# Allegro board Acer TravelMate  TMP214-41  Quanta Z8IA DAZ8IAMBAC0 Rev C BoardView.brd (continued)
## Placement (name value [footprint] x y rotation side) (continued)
C96764  2.2u/10V_4  [C0402]  92.37 113.94 270 top
C96765  10u/6.3V_4  [C0402]  133.9 131.21 90 top
C96766  47u/6.3V_6  [C0603]  117.8 119.91 0 top
C96767  4.7u/6.3V_4  [C0402]  111.42 116.99 90 bottom
C96768  1u/10V_2  [C0201]  107.95 130.6 270 top
C96769  1u/10V_2  [C0201]  105.71 111.27 0 top
C96770  0.1u/6.3V_2  [C0201]  105.71 112.04 0 top
C96771  *1u/10V_2  [C0201]  105.71 110.51 0 top
C96772  *1u/10V_2  [C0201]  104.57 112.16 180 top
C96773  1u/10V_2  [C0201]  103.88 109.88 270 bottom
C96774  0.1u/6.3V_2  [C0201]  103.55 111.91 270 bottom
C96776  HUB@0.1u/6.3V_2  [C0201]  77.29 117.37 270 top
C96777  HUB@22p/25V_2  [C0201]  85.39 112.87 90 top
C96778  HUB@22p/25V_2  [C0201]  85.39 111.07 270 top
C96779  HUB@1u/10V_2  [C0201]  82.39 116.74 90 top
C96780  HUB@0.1u/6.3V_2  [C0201]  81.33 107.51 0 top
C96781  HUB@0.1u/6.3V_2  [C0201]  77.26 110.26 90 top
C96782  HUB@1u/10V_2  [C0201]  85.77 114.45 180 top
C96783  HUB@1u/10V_2  [C0201]  81.33 108.23 0 top
C96784  HUB@0.1u/6.3V_2  [C0201]  85.26 110.21 180 top
C96785  HUB@10u/6.3V_4  [C0402]  85.64 115.34 0 top
C96786  HUB@0.1u/6.3V_2  [C0201]  76.5 110.26 90 top
C96788  SM@470p/50V_4  [C0402]  224.07 91.72 90 top
C96789  SM@0.1u/6.3V_2  [C0201]  225.09 91.46 270 top
C96790  SM@22u/6.3V_6  [C0603]  226.87 91.21 0 top
C96791  0.1u/6.3V_2  [C0201]  128.06 140.74 90 bottom
C96792  0.1u/6.3V_2  [C0201]  128.82 140.74 90 bottom
C96793  0.1u/6.3V_2  [C0201]  120.31 108.99 270 bottom
C96794  1u/10V_2  [C0201]  131.24 103.65 270 bottom
C96795  22p/25V_2  [C0201]  120.31 106.45 270 bottom
C96796  100p/50V_2  [C0201]  169.59 98.29 90 top
C96797  1000p/25V_2  [C0201]  170.73 101.22 90 top
C96798  0.22u/25V_2  [C0201]  24.72 64.65 180 top
C96799  0.22u/25V_2  [C0201]  24.72 65.41 180 top
C96800  0.22u/25V_2  [C0201]  24.72 66.17 180 top
C96801  0.33u/25V_2  [C0201]  11.73 70.25 180 bottom
C96802  0.33u/25V_2  [C0201]  11.73 69.49 180 bottom
C96803  0.22u/25V_2  [C0201]  24.72 63.88 180 top
C96804  0.22u/25V_2  [C0201]  11.73 70.25 180 top
C96805  0.22u/25V_2  [C0201]  11.73 69.49 180 top
C96806  0.22u/25V_2  [C0201]  24.72 61.6 180 top
C96807  0.22u/25V_2  [C0201]  24.72 60.84 180 top
C96808  0.33u/25V_2  [C0201]  11.73 62.25 180 top
C96809  0.33u/25V_2  [C0201]  11.73 63.01 180 top
C96810  0.22u/25V_2  [C0201]  24.72 62.36 180 top
C96811  0.22u/25V_2  [C0201]  24.72 63.12 180 top
C96812  0.22u/25V_2  [C0201]  11.73 62.25 180 bottom
C96813  0.22u/25V_2  [C0201]  11.73 63.01 180 bottom
C96814  10p/25V_2  [C0201]  20.11 68.09 180 top
C96815  10p/25V_2  [C0201]  18.99 68.09 0 top
C96816  2.2u/10V_4  [C0402]  19.98 63.55 0 bottom
C96817  47u/6.3V_6  [C0603]  22.8 68.35 270 bottom
C96818  2.2u/10V_4  [C0402]  21.48 67.92 270 bottom
C96819  2.2u/10V_4  [C0402]  23.03 65.55 270 bottom
C96820  2.2u/10V_4  [C0402]  21.76 63.52 180 bottom
C96821  2.2u/10V_4  [C0402]  17.85 67.21 90 bottom
C96822  10u/6.3V_4  [C0402]  16.89 67.21 90 bottom
C96823  18p/25V_2  [C0201]  18.84 66.8 270 bottom
C96824  2.2u/10V_4  [C0402]  23.13 63.8 270 bottom
C96825  10u/6.3V_4  [C0402]  20.11 66.82 180 bottom
C96826  2.2u/10V_4  [C0402]  19.73 68.22 180 bottom
C96827  47u/6.3V_6  [C0603]  23.67 73.43 90 top
C96828  18p/25V_2  [C0201]  25.45 75.46 180 top
C96829  47u/6.3V_6  [C0603]  22.25 73.43 90 top
C96830  2.2u/10V_4  [C0402]  23.03 62 270 bottom
C96831  2.2u/10V_4  [C0402]  18.33 65.43 90 bottom
C96832  2.2u/10V_4  [C0402]  18.33 63.65 90 bottom
C96833  2.2u/10V_4  [C0402]  18.33 61.87 270 bottom
C96834  2.2u/10V_4  [C0402]  16.94 65.43 90 bottom
C96835  47u/6.3V_6  [C0603]  33.19 65.43 90 top
C96836  2.2u/10V_4  [C0402]  29 64.28 270 top
C96837  0.1u/6.3V_2  [C0201]  33.57 71.14 0 top
C96851  47u/6.3V_6  [C0603]  5.3 45.79 90 bottom
C96852  47u/6.3V_6  [C0603]  6.75 45.77 90 bottom
C96853  47u/6.3V_6  [C0603]  8.17 45.79 90 bottom
C96854  10u/6.3V_4  [C0402]  8.81 47.6 0 bottom
C96855  10u/25V_8  [C0805]  10.46 52.47 270 bottom
C96856  0.47u/25V_2  [C0201]  11.09 67.92 90 top
C96857  0.47u/25V_2  [C0201]  10.43 64.67 180 top
C96858  0.47u/25V_2  [C0201]  10.33 67.92 90 top
C96859  0.47u/25V_2  [C0201]  10.43 65.38 180 top
C96861  1u/10V_2  [C0201]  14.45 55.14 180 bottom
C96862  1u/10V_2  [C0201]  13.89 45.18 270 bottom
C96863  0.1u/25V_2  [C0201]  14.45 55.9 180 bottom
C96864  0.1u/25V_2  [C0201]  15.54 55.9 0 bottom
C96865  0.1u/25V_2  [C0201]  14.65 45.18 270 bottom
C96866  1u/10V_2  [C0201]  15.54 55.14 0 bottom
C96867  390p/50V_4  [C0402]  22.65 48.66 0 bottom
C96868  390p/50V_4  [C0402]  22.65 47.65 0 bottom
C96869  0.1u/25V_2  [C0201]  22.27 46.76 0 bottom
C96870  **0.1u/6.3V_2  [C0201]  205.02 116.35 90 bottom
C96871  10u/6.3V_4  [C0402]  194.99 104.8 0 bottom
C96872  0.1u/6.3V_2  [C0201]  194.23 103.4 90 bottom
C96873  0.01u/10V_2  [C0201]  194.99 103.4 90 bottom
C96876  47u/6.3V_8  [C0805]  199.05 120.93 0 bottom
C96878  **1000p/25V_2  [C0201]  204.26 116.35 90 bottom
C96879  EX-IO@0.1u/6.3V_2  [C0201]  133.9 127.53 0 bottom
C96880  EX-IO@0.1u/6.3V_2  [C0201]  135.94 118.03 90 bottom
C96881  EX-IO@1u/10V_2  [C0201]  139.49 120.8 0 bottom
C96882  22u/6.3V_6  [C0603]  208.33 123.72 0 bottom
C96883  *0.1u/6.3V_2  [C0201]  204.26 113.81 180 top
C96884  *0.1u/6.3V_2  [C0201]  205.15 108.73 270 top
C96885  *1000p/25V_2  [C0201]  209.24 118.28 180 bottom
C96886  0.047u/25V_4  [C0402]  209.14 119.15 0 bottom
C96887  0.1u/6.3V_2  [C0201]  207.77 119.25 180 bottom
C96888  *10u/6.3V_4  [C0402]  207.41 118.39 0 bottom
C96889  0.1u/6.3V_2  [C0201]  207.18 113.81 0 top
C96890  0.1u/6.3V_2  [C0201]  209.47 113.81 0 top
C96891  *debug2@0.1u/6.3V_2  [C0201]  168.7 141.25 0 top
C96892  22u/6.3V_6  [C0603]  170.1 137.31 0 bottom
C96893  *1000p/25V_2  [C0201]  166.8 139.72 90 bottom
C96894  0.1u/6.3V_2  [C0201]  167.79 147.93 180 top
C96895  0.1u/6.3V_2  [C0201]  166.8 140.74 270 bottom
C96896  *10u/6.3V_4  [C0402]  165.91 140.36 90 bottom
C96897  *0.1u/6.3V_2  [C0201]  169.72 141.25 180 top
C96898  *0.1u/6.3V_2  [C0201]  171.01 145.18 90 bottom
C96901  2.2u/10V_4  [C0402]  33.57 70.25 0 top
C96902  2.2u/10V_4  [C0402]  28.62 65.68 180 top
C96903  0.1u/6.3V_2  [C0201]  77.85 101.37 0 top
C96904  *0.1u/6.3V_2  [C0201]  170.86 146.2 0 bottom
C96905  0.33u/25V_2  [C0201]  81.96 121.43 270 top
C96906  2.2u/10V_4  [C0402]  30.65 40.79 270 bottom
C96907  SPIN@0.1u/6.3V_2  [C0201]  142.03 213.48 0 top
C96908  *100p/50V_2  [C0201]  3.98 53.11 180 bottom
C96909  6800p/50V_4  [C0402]  3.98 54 0 bottom
C96910  0.1u/25V_2  [C0201]  3.98 48.59 0 bottom
C96911  0.1u/25V_2  [C0201]  3.98 51.58 0 bottom
C96912  *EX-IO@0.1u/6.3V_2  [C0201]  139.24 127.02 90 bottom
C96913  *EX-IO@0.1u/6.3V_2  [C0201]  135.81 130.32 0 bottom
C96918  **HDD_MS@0.1u/6.3V_2  [C0201]  232.07 125.63 0 top
C96919  *HDD_MS@0.1u/6.3V_2  [C0201]  232.84 120.93 0 top
C96920  **HDD_MS@0.1u/6.3V_2  [C0201]  216.2 104.67 180 top
C96921  *HDD_MS@0.1u/6.3V_2  [C0201]  218.87 108.1 180 top
C96922  I219@0.1u/6.3V_2  [C0201]  16.38 164.23 90 bottom
C96923  I219@0.1u/6.3V_2  [C0201]  14.9 164.23 90 bottom
C96924  I219@0.1u/6.3V_2  [C0201]  14.14 164.23 90 bottom
C96925  ViKi@1000p/25V_2  [C0201]  44.5 96.54 90 top
C96926  ViKi@1000p/25V_2  [C0201]  43.48 96.54 90 top
C96927  ViKi@1000p/25V_2  [C0201]  42.21 96.16 0 top
C96928  ViKi@1000p/25V_2  [C0201]  46.02 96.67 180 top
C96929  **SSD_MS@0.1u/6.3V_2  [C0201]  18.08 78.89 90 top
C96930  *SSD_MS@0.1u/6.3V_2  [C0201]  23.67 77.24 180 top
C96931  0.1u/6.3V_2  [C0201]  106.98 111.32 0 bottom
CN1  50271-0020N-001  [50271-00201-001-2P-L]  6.3 10.83 270 bottom
CN2  USB-097-1R09HG  [UB3-USB-097-1R09HG-9P]  8.4 89.12 90 bottom
CN3  USB-097-1R09HG  [UB3-USB-097-1R09HG-9P]  8.4 107.22 90 bottom
CN4  SPIN@50506-0060N-V01  [FPC-50506-0060N-V01-6P-L]  85.9 96.8 180 bottom
CN8  2RJ1622-001111F  [RJ45-2RJ1622-001111F-8P]  11.05 184.7 90 bottom
CN10  560Q10-010H  [UB31-560Q10-010H-24P]  8.51 66.67 90 bottom
CN11  HDD@GS12201-1011-7H  [WTB-GS12201-1011-7H-20P-L-SMT]  229.89 105.5 0 bottom
CN13  50505-00401-V01  [50505-00401-V01-4P-L]  224.85 135.4 270 bottom
CN14  SPIN_N@196241-08021-3  [196241-08021-3-8P-L]  75.7 96.95 180 bottom
CN16  SSD@NASM0-S6701-TSH4  [NGFF-NASM0-S6701-TSH4-KM-SMT]  25.1 75.1 180 bottom
CN17  NASE0-S6701-TS40  [NGFF-NASE0-S6701-TS40-KE-SMT]  189.65 114.4 270 bottom
CN18  15@50584-0280N-V02  [50584-0280N-V02-28P-L]  182.54 98.8 180 bottom
CN19  14@50584-0280N-V02  [50584-0280N-V02-28P-L]  154.9 108 180 bottom
CN21  CRT@DHR4U-15K1202  [DSUB-DHR4U-15K1202-15P]  7.6 157.76 90 bottom
CN29  196538-40041-3  [196538-40041-3-40P-L]  66.4 196.1 0 bottom
CN33  196047-08021-3  [196047-08021-3-8P-L]  129.6 97.05 180 bottom
CN37  10591-19001  [HDMI-10591-19001-19P]  4.4 127.48 90 bottom
CN46  SPIN@50271-0020N-001  [50271-00201-001-2P-L]  52.1 95.9 180 bottom
CN48  P2_P2SPIN@51540-02201-V01  [FPC-51540-02201-V01-22P-L]  207.2 110.12 180 bottom
CN49  LTE@51540-03001-V01  [51540-03001-V01-30P-L]  225.75 120.5 270 bottom
CN50  IR@50208-00601-V02  [50208-00601-V02-6P-L]  34.57 195.85 0 bottom
CN51  2SJ3127-023111F  [AUDIO-2SJ3127-023111F-6P]  5.42 21.46 90 bottom
CN52  SPIN@51619-01601-V01  [51619-01601-V01-16P-L]  207.1 98.15 180 bottom
CN53  SM@51653-0100N-V01  [51653-0100N-V01-10P-L]  222.4 98.05 180 bottom
CN55  ViKi@51619-01601-V01  [51619-01601-V01-16P-L]  231.85 121.21 270 bottom
CN58  NFC@51619-01501-V03  [51619-01501-V03-15P-L]  64.2 96.85 180 bottom
CN62  156-1000302610  [SDCARD-156-1000302610-11P-SMT]  13.3 43.05 270 top
CN63  P2_P2SPIN@50271-0040N-V01  [50271-0040N-V01-4P-L]  92.15 202.83 90 bottom
CN64  ViKi@50271-0040N-V01  [50271-0040N-V01-4P-L]  41.5 94.87 180 bottom
CN66  debug@51614-00601-V01  [51614-00601-V01-6P-L]  205.15 92.1 0 top
CN67  SPIN@50208-00601-V02  [50208-00601-V02-6P-L]  50.5 199.85 0 bottom
D3  1N4148WS  [D-SOD323-1_85X1_25-0_95H]  86.56 192.6 270 bottom
D4  EV@RB500V-40  [D-SOD323-1_85X1_25-0_95H]  108.76 185.32 90 top
D10  AZ5725-01F.R7G  [ESD-1X0_6-2P]  4.04 14.75 180 top
D11  1N4148WS  [D-SOD323-1_85X1_25-0_95H]  24.93 24.22 270 bottom
D12  *RB500V-40  [D-SOD323-1_85X1_25-0_95H]  32.56 31.77 180 bottom
D13  RB500V-40  [D-SOD323-1_85X1_25-0_95H]  32.56 33.68 180 bottom
D22  *PESD5V0H1BSF  [D-0_6X0_3-0_32H-SMT]  92.38 99.08 270 top
D33  AZ5725-01F.R7G  [ESD-1X0_6-2P]  194.74 97.69 0 top
D50  AZ5725-01F.R7G  [ESD-1X0_6-2P]  15.01 129.9 90 bottom
D51  *RB500V-40  [D-SOD323-1_85X1_25-0_95H]  141.17 103.91 180 top
D60  *RB500V-40  [D-SOD323-1_85X1_25-0_95H]  141.17 102 180 top
D62  *RB500V-40  [D-SOD323-1_85X1_25-0_95H]  141.27 100.1 0 top
D63  RB500V-40  [D-SOD323-1_85X1_25-0_95H]  144.95 103.93 0 top
D64  *RB500V-40  [D-SOD323-1_85X1_25-0_95H]  141.45 105.79 180 top
D65  TVM0G5R5M220R_22p  [R0402]  160.68 115.29 270 top
D72  BAT54CW  [SOT23-1_7-65-3P]  77.9 98.7 270 top
D6543  1N4148WS  [D-SOD323-1_85X1_25-0_95H]  23.07 22.5 270 bottom
D13081  *PESD5V0H1BSF  [D-0_6X0_3-0_32H-SMT]  15.67 126.97 270 bottom
D13082  *PESD5V0H1BSF  [D-0_6X0_3-0_32H-SMT]  15.67 125.93 90 bottom
D13083  *PESD5V0H1BSF  [D-0_6X0_3-0_32H-SMT]  15.45 125.54 0 top
D13084  *PESD5V0H1BSF  [D-0_6X0_3-0_32H-SMT]  15.45 124.48 0 top
D13085  *PESD5V0H1BSF  [D-0_6X0_3-0_32H-SMT]  15.01 121.92 0 top
D13086  *PESD5V0H1BSF  [D-0_6X0_3-0_32H-SMT]  15.01 120.86 0 top
D13087  *PESD5V0H1BSF  [D-0_6X0_3-0_32H-SMT]  15.52 128.84 0 top
D13088  *PESD5V0H1BSF  [D-0_6X0_3-0_32H-SMT]  15.52 127.75 0 top
D13089  *PESD5V0H1BSF  [D-0_6X0_3-0_32H-SMT]  14.52 131.21 270 top
D13090  *PESD5V0H1BSF  [D-0_6X0_3-0_32H-SMT]  14.52 130.07 90 top
D13091  *TVM0G5R5M220R_22p  [R0402]  147.62 209.57 0 top
D13092  *TVM0G5R5M220R_22p  [R0402]  151.05 210.72 180 top
D13093  SPIN_EXT@RB500V-40  [D-SOD323-1_85X1_25-0_95H]  155.49 212.87 180 bottom
D13094  AZ5725-01F.R7G  [ESD-1X0_6-2P]  7.06 29.98 90 bottom
D13095  AZ5725-01F.R7G  [ESD-1X0_6-2P]  11.09 14.37 270 top
D13096  P4SMAFJ20A  [D-3_8X2_5]  11.43 57.93 90 bottom
D13101  TVM0G5R5M261R_260p  [R0402]  18 88.92 90 bottom
D13102  TVM0G5R5M261R_260p  [R0402]  18.59 110.97 180 top
D13106  RB500V-40  [D-SOD323-1_85X1_25-0_95H]  92.07 109.14 0 top
D13107  RB500V-40  [D-SOD323-1_85X1_25-0_95H]  94.74 108.1 270 top
D13108  *RB500V-40  [D-SOD323-1_85X1_25-0_95H]  97.35 107.46 90 top
D13110  *HUB@SDM20U30-7  [D-1_2X0_8-0_7H]  84.98 117.5 270 top
D13111  *PESD5V0F1BSF  [D-0_6X0_3-0_32H-SMT]  61.03 191.28 180 bottom
D13112  *PESD5V0F1BSF  [D-0_6X0_3-0_32H-SMT]  59.99 191.28 0 bottom
D13113  *PESD5V0F1BSF  [D-0_6X0_3-0_32H-SMT]  57.55 191.28 0 bottom
D13114  *PESD5V0F1BSF  [D-0_6X0_3-0_32H-SMT]  58.59 191.28 180 bottom
D13118  PESD5V0F1BSF  [D-0_6X0_3-0_32H-SMT]  10.59 72.54 90 bottom
D13119  PESD5V0F1BSF  [D-0_6X0_3-0_32H-SMT]  10.46 65.3 270 bottom
D13142  PESD5V0F1BSF  [D-0_6X0_3-0_32H-SMT]  8.94 67.21 90 top
D13143  PESD5V0F1BSF  [D-0_6X0_3-0_32H-SMT]  8.94 66.09 270 top
D13144  PESD5V0F1BSF  [D-0_6X0_3-0_32H-SMT]  10.46 66.37 270 bottom
D13145  PESD5V0F1BSF  [D-0_6X0_3-0_32H-SMT]  10.46 67.41 90 bottom
D13146  PESD5V0F1BSF  [D-0_6X0_3-0_32H-SMT]  12.62 71.93 90 bottom
D13147  PESD5V0F1BSF  [D-0_6X0_3-0_32H-SMT]  11.35 67.97 270 bottom
D13148  EX-IO@RB500V-40  [D-SOD323-1_85X1_25-0_95H]  142.54 122.7 270 bottom
D13149  *BAT54CW  [SOT23-1_7-65-3P]  202.59 108.86 270 top
D13150  *BAT54CW  [SOT23-1_7-65-3P]  202.61 111.91 270 top
D13151  PESD5V0H1BSF  [D-0_6X0_3-0_32H-SMT]  12.87 70.38 90 bottom
D13152  PESD5V0H1BSF  [D-0_6X0_3-0_32H-SMT]  12.87 69.34 270 bottom
D13153  PESD5V0H1BSF  [D-0_6X0_3-0_32H-SMT]  12.87 70.38 90 top
D13154  PESD5V0H1BSF  [D-0_6X0_3-0_32H-SMT]  12.87 69.34 270 top
D13155  PESD5V0H1BSF  [D-0_6X0_3-0_32H-SMT]  12.87 62.1 270 top
D13156  PESD5V0H1BSF  [D-0_6X0_3-0_32H-SMT]  12.87 63.14 90 top
D13157  PESD5V0H1BSF  [D-0_6X0_3-0_32H-SMT]  12.87 62.1 270 bottom
D13158  PESD5V0H1BSF  [D-0_6X0_3-0_32H-SMT]  12.87 63.14 90 bottom
D13160  RB500V-40  [D-SOD323-1_85X1_25-0_95H]  30.37 44.6 90 bottom
D13161  *EV@RB500V-40  [D-SOD323-1_85X1_25-0_95H]  115.79 178.63 180 top
D13162  PESD5V0F1BSF  [D-0_6X0_3-0_32H-SMT]  18.54 87.88 270 top
D13163  PESD5V0F1BSF  [D-0_6X0_3-0_32H-SMT]  18.54 89.02 90 top
D13164  PESD5V0F1BSF  [D-0_6X0_3-0_32H-SMT]  18.21 104.54 90 top
D13165  PESD5V0F1BSF  [D-0_6X0_3-0_32H-SMT]  18.21 103.4 270 top
DG4  EV@BAT54AW-L  [SOT23-1_7-65-3P]  109.44 176.73 270 bottom
EC5  180p/25V_2  [C0201]  44.3 135.22 90 top
EC6  180p/25V_2  [C0201]  54.81 119.29 90 top
EC7  SPIN_N@AZ5725-01F.R7G  [ESD-1X0_6-2P]  93.39 101.55 270 bottom
EC8  SPIN_N@AZ5725-01F.R7G  [ESD-1X0_6-2P]  93.39 99.72 270 bottom
EC9  SSD@10u/6.3V_4  [C0402]  32.05 68.6 270 bottom
EC10  SSD@10u/6.3V_4  [C0402]  26.46 70.13 0 bottom
EC11  SSD@0.1u/6.3V_2  [C0201]  26.46 69.26 180 bottom
EC16  SPIN@AZ5725-01F.R7G  [ESD-1X0_6-2P]  208.57 99.05 180 top
EC17  SPIN@AZ5725-01F.R7G  [ESD-1X0_6-2P]  206.72 99.05 180 top
ESD3  CRT@AZ1045-04F.R7G  [ESD10-2_5X1-5-9P-AZ1143]  11.35 155.19 90 top
ESD4  CRT@AZ1045-04F.R7G  [ESD10-2_5X1-5-9P-AZ1143]  11.6 159.03 90 top
F1  SMD0603P100SLR_1A_6V  [R0603]  33.07 43.84 270 bottom
F2  SM@SMD0603P100SLR_1A_6V  [R0603]  217.6 103.27 90 top
FAN3  50278-00401-V01  [WTB-50278-00401-V01-4P-L]  176.02 117.8 90 bottom
HE1  APX8132AI-TRG  [SOT23-2_38-95-3P]  148.8 212.35 90 top
HOLE2  EV@H-TBC244IC166D126P2  [H-TBC244IC166D126P2]  116.52 212.65 180 bottom
HOLE3  EV@H-TBC244IC166D126P2  [H-TBC244IC166D126P2]  145.52 173.65 180 bottom
HOLE4  *H-TBC264IC146D146P2  [H-TBC264IC146D146P2]  97.87 114.15 0 top
HOLE5  *H-TBC264IC146D146P2  [H-TBC264IC146D146P2]  132.87 145.16 0 top
HOLE6  *H-TBC264IC146D146P2  [H-TBC264IC146D146P2]  97.87 176.15 0 top
HOLE12  -  [H-TBC236IC166D126P2]  217.95 114.4 180 bottom
HOLE13  *H-TC354IC158BC315D118P2  [H-TC354IC158BC315D118P2]  217.5 129.3 0 top
HOLE14  *h-z8ia-1p2  [H-Z8IA-1P2]  30.7 91.3 0 top
HOLE15  *O-Z8I-2P2  [O-Z8I-2P2]  164.3 216.3 0 top
HOLE16  *O-Z8I-1P2  [O-Z8I-1P2]  124.2 216.3 0 top
HOLE17  *h-z8ia-5p2  [H-Z8IA-5P2]  42.2 197.3 0 top
HOLE18  *H-TBC354IC158D118P2  [H-TBC354IC158D118P2]  177.8 106.58 0 top
HOLE21  *H-C354D177P2  [H-C354D177P2]  234 88.2 0 top
HOLE22  *O-Z8IA-B2P2  [O-Z8IA-B2P2]  12.2 140.3 0 top
HOLE23  *H-C315D118P2  [H-C315D118P2]  8.2 2.5 0 top
HOLE24  *h-z8i-1p2  [H-Z8I-1P2]  5.7 77.2 0 top
HOLE27  *O-Z8IA-B1P2  [O-Z8IA-B1P2]  7 172.36 0 top
HOLE28  *H-C106X87D106X87N  [H-C106X87D106X87N]  3.6 5.75 90 top
HOLE31  *H-C87D87N  [H-C87D87N]  6.8 139.5 0 top
HOLE32  *O-ZI8-3P2  [O-ZI8-3P2]  11.1 208.2 0 top
HOLE33  *2d-barcode-8x8-s  [2D-BARCODE-8X8-S]  30.42 191.28 180 top
HOLE34  *2d-barcode-8x8-s  [2D-BARCODE-8X8-S]  20.26 184.63 90 bottom
HOLE35  *H-S157D157N  [H-S157D157N]  136.16 158.8 0 top
J9007  *JUMP  [JOPEN25X30_S]  82.21 105.94 270 top
JDIM1  D4AS0-26001-1P40  [DDR4-D4AS0-26001-1P40-STD-SMT]  49.23 138.2 270 bottom
JDIM02  D4AR0-26001-1P40  [DDR4-D4AR0-26001-1P40-RVS-SMT]  61.23 138.2 90 bottom
L4  EV@HCB1005KF-330T30_3A  [R0402]  131.56 187.73 0 top
L5  *EV@HCB1608KF-301T20_2A  [R0603]  114.59 192.55 0 top
L6  EV@HCB1005KF-330T30_3A  [R0402]  112.99 190.97 0 top
L7  EV@HCB1005KF-330T30_3A  [R0402]  114.45 195.91 90 top
L8  EV@HCB1005KF-330T30_3A  [R0402]  114.45 197.64 270 top
L11  BLM15AG121SN1D_0.5A  [R0402]  172.89 101.88 180 top
L12  BLM15AG601SN1D_0.3A  [R0402]  52.12 191.92 0 bottom
L13  BLM15AG601SN1D_0.3A  [R0402]  52.12 190.9 0 bottom
L15  PBY160808T-600Y-N_3A  [R0603]  23 40.75 0 bottom
L16  HCB2012KF-220T60_6A  [R0805]  10.7 31.76 180 bottom
L17  CRT@PBY160808T-600Y-N_3A  [R0603]  28.62 145.82 270 top
L22  CRT@BLM15BB470SN1D_0.3A  [R0402]  17.44 153.06 0 top
L23  HCB1005KF-330T30_3A  [R0402]  134.41 96.8 90 top
L24  HCB1005KF-330T30_3A  [R0402]  131.69 96.47 0 top
L27  CRT@BLM15BB470SN1D_0.3A  [R0402]  17.71 154.73 0 top
L28  HCB1608KF-121T30_3A  [R0603]  14.85 38.38 180 bottom
L29  BLM15AG121SN1D_0.5A  [R0402]  172.92 100.86 0 top
L30  BLM15AG121SN1D_0.5A  [R0402]  150.16 112.29 90 top
L31  CRT@BLM15BB470SN1D_0.3A  [R0402]  18.22 156.47 0 top
L4000  I219@4.7uH_3.2x2.5x2  [L3_2X2_5-3_2]  14.9 160.68 0 bottom
L4001  0.68uH_2.5x2.0x1.2  [L2_5X2-1_2H]  25.83 73.48 90 top
L4002  BLM15PD121SN1D_1.3A  [R0402]  28.62 66.7 0 top
L4003  CRT@PBY160808T-600Y-N_3A  [R0603]  36.88 148.43 0 top
LH1  NFP0QHB372HS2D  [FILTER-NFG0QHB372HS2D-4P-SMT]  18.84 129.44 180 top
NOREF  -  []  212.39 13.23 0 top
NOREF#2  -  [unnamed#2]  224.58 128.93 0 top
NOREF#3  -  []  224.96 136.21 0 top
NOREF#4  -  [unnamed#2]  16.05 191.67 0 top
NOREF#5  -  []  50.98 6.36 0 top
NOREF#6  -  [unnamed#2]  27.26 25.88 0 top
NOREF#7  -  []  235.05 97.17 180 bottom
NOREF#8  -  [unnamed#2]  231.82 100.63 180 bottom
NOREF#9  -  [unnamed#2]  27.1 193.95 180 bottom
NOREF#10  -  [unnamed#2]  17.22 15.67 180 bottom
PC1  1000p/50V_4  [C0402]  69.41 200.35 90 top
PC2  0.047u/50V_6  [C0603]  73.93 198.42 180 top
PC3  0.1u/25V_4  [C0402]  157.75 114.17 0 bottom
PC4  0.1u/25V_4  [C0402]  158.41 112.98 0 bottom
PC5  0.1u/50V_4  [C0402]  69.41 202.1 270 top
PC6  0.1u/25V_4  [C0402]  156.64 112.98 180 bottom
PC7  2200p/50V_4  [C0402]  150.03 129.56 0 top
PC8  0.01u/50V_4  [C0402]  155.87 116.53 90 bottom
PC9  2.2u/10V_4  [C0402]  155.19 118.31 90 bottom
PC10  *47p/50V_4  [C0402]  111.2 105.31 90 bottom
PC11  *47p/50V_4  [C0402]  107.84 104.75 0 bottom
PC12  0.1u/50V_4  [C0402]  150.03 130.83 0 top
PC15  0.047u/50V_6  [C0603]  153.79 121.01 0 top
PC16  0.47u/25V_6  [C0603]  155.16 121.79 0 bottom
PC17  *0.01u/50V_4  [C0402]  148.51 118.26 180 top
PC18  *100p/50V_4  [C0402]  165.21 119.18 0 bottom
PC19  *680p/50V_6  [C0603]  153.64 114.53 270 bottom
PC25  0.1u/50V_4  [C0402]  158.33 122.99 0 bottom
PC35  0.1u/50V_4  [C0402]  158.56 124.34 270 bottom
PC36  0.1u/50V_4  [C0402]  159.53 124.34 90 bottom
PC37  100p/50V_4  [C0402]  167.43 123.42 0 bottom
PC51  2200p/50V_4  [C0402]  59.62 179.19 90 top
PC73  100p/50V_4  [C0402]  165.15 121.18 0 bottom
PC164  22u/25V_8  [C0805]  136.27 113.26 90 bottom
PC165  2200p/50V_4  [C0402]  139.72 112.37 90 bottom
PC166  22u/25V_8  [C0805]  138.25 113 90 bottom
PC167  0.1u/50V_4  [C0402]  110.79 103.02 90 top
PC168  *100p/50V_4  [C0402]  111.81 103.02 270 top
PC170  10u/25V_6  [C0603]  153.39 119.33 90 bottom
PC172  2200p/50V_4  [C0402]  151.68 119.35 90 top
PC229  *10u/6.3V_6  [C0603]  7.41 37.41 90 bottom
PC242  *4.7u/6.3V_4  [C0402_2]  3.91 32.38 180 bottom
PC551  *2200p/50V_6  [C0603]  34.59 141.25 90 top
PC561  0.1u/6.3V_2  [C0201]  38.91 135.79 0 top
PC562  22u/6.3V_6  [C0603]  34.97 134.64 0 top
PC563  22u/6.3V_6  [C0603]  37.76 134.64 180 top
PC571  10u/6.3V_4  [C0402_2]  35.35 143.91 270 top
PC572  0.01u/50V_4  [C0402]  36.49 143.91 270 top
PC574  *22p/50V_4  [C0402]  38.65 142.01 270 top
PC581  0.1u/6.3V_2  [C0201]  38.65 139.09 0 top
PC756  *0.1u/16V_4  [C0402]  164.73 118.09 180 bottom
PC5000  *0.1u/50V_4  [C0402]  91.36 171.9 270 top
PC5001  *0.1u/50V_4  [C0402]  92.32 171.9 270 top
PC5002  0.1u/50V_4  [C0402]  84.58 178.46 90 top
PC5003  10u/25V_6  [C0603]  88.39 182.01 270 bottom
PC5004  10u/25V_6  [C0603]  90.39 182.01 270 bottom
PC5005  2200p/50V_4  [C0402]  83.61 178.46 90 top
PC5006  10u/6.3V_4  [C0402]  87.42 173.63 0 top
PC5007  0.1u/50V_4  [C0402]  85.54 178.46 90 top
PC5008  0.1u/50V_4  [C0402]  88.01 178.51 270 top
PC5009  0.1u/50V_4  [C0402]  72.18 177.97 90 top
PC5010  22u/6.3V_8  [C0805]  72.87 183.26 270 bottom
PC5011  22u/6.3V_8  [C0805]  70.78 179.68 90 bottom
PC5012  22u/6.3V_8  [C0805]  72.82 179.68 90 bottom
PC5013  0.1u/50V_4  [C0402]  89.25 171.17 90 top
PC5014  0.047u/25V_4  [C0402]  90.22 171.22 90 top
PC5015  22u/6.3V_8  [C0805]  70.86 183.26 270 bottom
PC5016  *330u/2V_7343H1.9  [CC7343]  66.7 179.98 180 top
PC5017  *10u/6.3V_6  [C0603]  86.23 175.23 0 top
PC5018  *680p/50V_6  [C0603]  85.85 186.64 90 bottom
PC5019  1u/6.3V_2  [C0201]  89.71 180.11 180 top
PC5020  10u/6.3V_4  [C0402]  72.44 184.63 180 top
PC5021  10u/6.3V_6  [C0603]  79.07 186.81 270 bottom
PC5022  *10u/6.3V_6  [C0603]  80.49 186.81 270 bottom
PC5023  0.1u/50V_4  [C0402]  78.15 185.06 90 top
PC5024  *0.47u/6.3V_4  [C0402]  75.15 189.1 90 bottom
PC6000  0.1u/25V_4  [C0402]  175.74 127.56 180 top
PC6001  0.1u/25V_4  [C0402]  180.84 134.18 180 bottom
PC6002  2200p/50V_4  [C0402]  175.76 125.52 0 top
PC6003  0.1u/25V_4  [C0402]  175.76 126.54 0 top
PC6004  10u/25V_6  [C0603]  177.08 126.44 90 bottom
PC6005  10u/25V_6  [C0603]  175.08 126.44 90 bottom
PC6006  *680p/50V_6  [C0603]  179.45 125.42 0 bottom
PC6007  0.1u/16V_4  [C0402]  176.02 128.92 0 top
PC6008  22u/6.3V_6  [C0603]  189.7 130.35 270 bottom
PC6009  22u/6.3V_6  [C0603]  191.13 130.35 270 bottom
PC6010  22u/6.3V_6  [C0603]  192.56 127.71 90 bottom
PC6011  *22u/6.3V_6  [C0603]  192.57 130.35 270 bottom
PC6012  *22u/6.3V_6  [C0603]  191.13 127.71 90 bottom
PC6013  0.1u/16V_4  [C0402]  184.42 134.06 0 bottom
PC6014  22u/6.3V_6  [C0603]  189.68 127.71 90 bottom
PC6015  1u/25V_4  [C0402]  198.45 127.1 180 bottom
PC6016  1u/25V_4  [C0402]  198.84 130.57 270 bottom
PC6017  0.1u/16V_4  [C0402]  173.78 131.34 180 bottom
PC6018  10u/6.3V_6  [C0603]  203.75 126.01 90 bottom
PC6019  0.1u/16V_4  [C0402]  202.53 126.26 90 bottom
PC6020  0.1u/16V_4  [C0402]  204.82 129.94 270 bottom
PC6021  10u/6.3V_6  [C0603]  207.29 129.53 270 bottom
PC6022  1u/25V_4  [C0402]  173.78 130.35 0 bottom
PC6023  4.7u/6.3V_4  [C0402_2]  174.04 132.48 0 bottom
PC6024  10p/50V_4  [C0402]  173.18 135.34 180 bottom
PC6025  0.1u/16V_4  [C0402]  200.41 129.74 270 top
PC6026  *0.1u/16V_4  [C0402]  200.14 128.02 180 top
PC6027  *0.1u/16V_4  [C0402]  199.43 130.51 270 top
PC6028  1000p/50V_4  [C0402]  207.49 127.71 0 bottom
PC6029  1000p/50V_4  [C0402]  205.38 128.37 180 bottom
PC6030  0.1u/25V_4  [C0402]  55.54 183.08 0 top
PC6031  0.1u/25V_4  [C0402]  55.54 184.07 180 top
PC6032  10u/25V_6  [C0603]  52.27 188.41 0 bottom
PC6033  10u/25V_6  [C0603]  52.27 186.43 0 bottom
PC6034  2200p/50V_4  [C0402]  55.54 185.04 180 top
PC6035  0.1u/25V_4  [C0402]  54.61 178.99 270 bottom
PC6036  1u/25V_4  [C0402]  38.74 165.04 90 top
PC6037  1u/25V_4  [C0402]  34.21 166.65 270 top
PC6038  *680p/50V_6  [C0603]  50.95 180.64 180 top
PC6039  0.1u/16V_4  [C0402]  56.56 186.94 90 bottom
PC6040  10u/6.3V_6  [C0603]  38.15 162.84 270 top
PC6041  0.1u/16V_4  [C0402]  38.57 161.03 180 top
PC6042  0.1u/16V_4  [C0402]  32.81 160.68 0 top
PC6043  10u/6.3V_6  [C0603]  32.94 162.51 270 top
PC6044  22u/6.3V_6  [C0603]  45.77 186.61 270 bottom
PC6045  22u/6.3V_6  [C0603]  49.32 188.85 180 bottom
PC6046  22u/6.3V_6  [C0603]  43.89 179.43 90 bottom
PC6047  22u/6.3V_6  [C0603]  47.21 186.61 270 bottom
PC6048  *22u/6.3V_6  [C0603]  49.32 187.42 180 bottom
PC6049  *22u/6.3V_6  [C0603]  49.32 186 180 bottom
PC6050  0.1u/16V_4  [C0402]  44.55 186.18 270 bottom
PC6051  0.1u/16V_4  [C0402]  36.24 166.65 270 top
PC6052  *0.1u/16V_4  [C0402]  37.26 166.65 270 top
PC6053  *0.1u/16V_4  [C0402]  35.22 166.65 270 top
PC6054  4.7u/10V_6  [C0603]  57.27 179.37 90 bottom
PC6055  0.1u/16V_4  [C0402]  59.1 181.33 270 bottom
PC6056  1000p/50V_4  [C0402]  36.04 160.44 90 top
PC6057  1000p/50V_4  [C0402]  34.97 160.42 90 top
PC6058  1u/25V_4  [C0402]  59.51 179.96 180 bottom
PC6059  10p/50V_4  [C0402]  61.44 181.81 0 bottom
PC6228  0.1u/16V_4  [C0402]  132 113.94 180 bottom
PC6229  *0.47u/6.3V_4  [C0402]  4.95 39.7 0 bottom
PC6230  *10u/6.3V_6  [C0603]  7.41 40.05 270 bottom
PC6231  *0.1u/16V_4  [C0402]  11.73 35.46 90 bottom
PC7000  *15u/25V_3528H1.9  [C3528]  158.92 152.93 180 bottom
PC7001  0.1u/6.3V_2  [C0201]  162.58 150.06 270 top
PC7002  4.7u/6.3V_4  [C0402_2]  162.28 145.36 315 top
PC7003  0.22u/25V_4  [C0402]  157.96 144.98 135 top
PC7004  10u/25V_6  [C0603]  154.6 159.36 0 bottom
PC7005  10u/25V_6  [C0603]  154.6 157.38 0 bottom
PC7006  10u/25V_6  [C0603]  154.6 153.31 0 bottom
PC7007  10u/25V_6  [C0603]  154.6 155.34 0 bottom
PC7008  0.1u/25V_4  [C0402]  159.46 155.22 180 bottom
PC7009  2200p/50V_4  [C0402]  159.43 156.23 0 bottom
PC7010  0.1u/25V_4  [C0402]  159.43 157.25 180 bottom
PC7011  2.2u/10V_4  [C0402]  158.08 146.81 45 top
PC7012  0.1u/25V_4  [C0402]  155.87 146.58 90 bottom
PC7013  22u/6.3V_6  [C0603]  114.93 172.36 180 bottom
PC7014  *22u/6.3V_6  [C0603]  114.93 173.78 180 bottom
PC7015  *22u/6.3V_6  [C0603]  129.33 159.41 90 bottom
PC7016  *22u/6.3V_6  [C0603]  110.15 173.68 0 bottom
PC7017  *22u/6.3V_6  [C0603]  110.15 172.26 0 bottom
PC7018  0.47u/6.3V_4  [C0402]  160.78 143.89 135 top
PC7019  *2200p/25V_2  [C0201]  142.44 146.38 0 bottom
PC7020  10u/25V_6  [C0603]  152.29 146.4 0 bottom
PC7021  10u/25V_6  [C0603]  152.29 144.42 0 bottom
PC7022  10u/25V_6  [C0603]  143.48 142.31 270 bottom
PC7023  10u/25V_6  [C0603]  141.47 142.31 270 bottom
PC7024  0.1u/25V_4  [C0402]  151.68 147.98 0 bottom
PC7025  2200p/50V_4  [C0402]  152.14 149.91 180 bottom
PC7026  0.1u/25V_4  [C0402]  151.68 148.94 0 bottom
PC7027  0.1u/25V_4  [C0402]  158.54 150.21 225 bottom
PC7028  22u/6.3V_6  [C0603]  130.86 159.41 90 bottom
PC7029  *330u/2.5V_7343H1.9  [CC7343]  130.96 169.19 90 bottom
PC7030  *330u/2.5V_7343H1.9  [CC7343]  140.63 163.98 90 bottom
PC7031  330u/2.5V_7343H1.9  [CC7343]  135.68 168.81 90 bottom
PC7032  *330u/2.5V_7343H1.9  [CC7343]  140.63 153.95 270 bottom
PC7033  *2200p/25V_2  [C0201]  151.13 167.08 180 bottom
PC7034  0.1u/25V_4  [C0402]  156.87 142.08 0 bottom
PC7035  0.1u/25V_4  [C0402]  158.06 139.77 90 bottom
PC7036  0.1u/25V_4  [C0402]  160.75 141.63 180 bottom
PC7037  0.1u/25V_4  [C0402]  159.02 139.77 90 bottom
PC7038  *0.1u/6.3V_2  [C0201]  155.44 142.21 0 bottom
PC7039  *100p/50V_4  [C0402]  164.49 142.14 180 bottom
PC7040  82p/50V_4  [C0402]  162.76 141.04 180 bottom
PC7041  390p/50V_4  [C0402]  164.49 141.17 0 bottom
PC7042  *0.1u/6.3V_2  [C0201]  165.65 144.55 90 bottom
PC7043  *100p/50V_4  [C0402]  163.11 142.39 270 bottom
PC7044  *100p/50V_4  [C0402]  164.49 143.1 180 bottom
PC7045  0.1u/25V_4  [C0402]  165.35 136.8 0 bottom
PC7046  10u/25V_6  [C0603]  153 135.84 0 bottom
PC7047  10u/25V_6  [C0603]  162.81 128.42 270 bottom
PC7048  10u/25V_6  [C0603]  153 133.8 0 bottom
PC7049  10u/25V_6  [C0603]  160.8 128.42 270 bottom
PC7050  0.1u/25V_4  [C0402]  165.32 126.26 90 bottom
PC7051  2200p/50V_4  [C0402]  164.36 126.26 270 bottom
PC7052  0.1u/25V_4  [C0402]  166.29 126.26 90 bottom
PC7053  0.1u/25V_4  [C0402]  160.09 132.84 90 bottom
PC7054  1u/6.3V_4  [C0402]  160.04 136.98 0 bottom
PC7055  0.1u/16V_4  [C0402]  135.05 135.66 90 bottom
PC7056  *22u/6.3V_6  [C0603]  136.7 135.66 90 bottom
PC7057  330u/2.5V_7343H1.9  [CC7343]  144.01 137.06 0 bottom
PC7058  22u/6.3V_6  [C0603]  136.7 132.74 270 bottom
PC7059  22u/6.3V_6  [C0603]  134.92 132.74 270 bottom
PC7060  *22u/6.3V_6  [C0603]  138.48 138.96 270 bottom
PC7061  *2200p/25V_2  [C0201]  147.75 131.59 270 top
PC7062  22u/6.3V_6  [C0603]  138.48 132.74 270 bottom
PC7063  22u/6.3V_6  [C0603]  134.92 138.96 270 bottom
PC7064  *22u/6.3V_6  [C0603]  138.48 135.66 90 bottom
PC7065  *22u/6.3V_6  [C0603]  136.7 138.96 270 bottom
PC7066  *0.1u/16V_4  [C0402]  163.98 137.99 90 bottom
PC7067  2200p/50V_4  [C0402]  167.89 133.55 180 bottom
PC7068  *470p/50V_4  [C0402]  165.96 131.29 90 bottom
PC7069  27p/50V_4  [C0402]  166.54 133.02 90 bottom
PC7070  *0.1u/25V_4  [C0402]  164 131.01 270 bottom
PC8000  0.1u/50V_6  [C0603]  33.55 103.3 180 top
PC8001  0.1u/50V_4  [C0402]  14.63 197.93 180 top
PC8002  2200p/50V_4  [C0402]  14.63 196.97 180 top
PC8003  0.1u/50V_6  [C0603]  61.89 198.62 180 top
PC8005  1u/25V_4  [C0402]  24.1 116.76 270 top
PC8006  2.2u/10V_4  [C0402]  18.09 117.09 270 top
PC8007  0.1u/25V_4  [C0402]  23.95 119.1 180 top
PC8008  *1u/25V_4  [C0402]  36.24 113.36 180 top
PC8009  *2.2u/10V_4  [C0402]  33.17 110.88 90 top
PC8010  *2.2u/10V_4  [C0402]  31.45 111.29 0 top
PC8011  *0.1u/25V_4  [C0402]  34.51 113.36 0 top
PC9000  EV@2.2u/10V_4  [C0402]  104.57 198.78 315 top
PC9001  EV@10u/25V_6  [C0603]  99.39 202.08 180 top
PC9002  EV@10u/25V_6  [C0603]  99.39 204.11 180 top
PC9003  EV@0.1u/25V_4  [C0402]  97.2 204.62 270 top
PC9004  EV@1u/25V_6  [C0603]  96.41 192.68 90 top
PC9005  EV@10u/25V_6  [C0603]  94.66 203.73 270 top
PC9006  EV@2200p/50V_4  [C0402]  96.18 204.62 270 top
PC9007  *EV@15u/25V_3528H1.9  [C3528]  90.98 203.73 180 top
PC9008  EV@0.22u/25V_6  [C0603]  102.23 199.97 0 top
PC9009  EV@22u/6.3V_8  [C0805]  113.24 203.93 90 top
PC9010  EV@330u/2V_7343H1.9  [CC7343]  106.04 207.85 225 top
PC9011  EV@330u/2V_7343H1.9  [CC7343]  144.06 215.03 0 bottom
PC9012  *EV@2200p/50V_4  [C0402]  104.95 200.48 90 bottom
PC9013  EV@0.22u/10V_4  [C0402]  99.49 198.95 270 top
PC9014  *EV@0.22u/10V_4  [C0402]  103.65 194.94 45 bottom
PC9015  EV@10u/25V_6  [C0603]  109.67 192.05 270 top
PC9016  EV@10u/25V_6  [C0603]  106.98 191.64 270 bottom
PC9017  EV@10u/25V_6  [C0603]  106.88 188.39 90 bottom
PC9018  EV@0.1u/25V_4  [C0402]  108.37 188.16 90 bottom
PC9019  EV@2200p/50V_4  [C0402]  109.33 188.16 90 bottom
PC9020  EV@0.22u/25V_6  [C0603]  105.96 196.31 90 top
PC9021  EV@330u/2V_7343H1.9  [CC7343]  109.88 200.94 270 top
PC9022  EV@22u/6.3V_8  [C0805]  134.64 210.53 0 bottom
PC9023  EV@0.1u/16V_4  [C0402]  96.64 194.48 0 top
PC9024  *EV@2200p/50V_4  [C0402]  107.39 196.06 90 bottom
PC9025  EV@4700p/25V_4  [C0402]  95.22 197.56 0 top
PC9026  EV@1500p/50V_4  [C0402]  97.06 195.45 0 top
PC9027  EV@56p/50V_4  [C0402]  101.95 191.77 180 top
PC9028  *EV@100p/50V_4  [C0402]  100.45 192.88 315 top
PC9029  EV@56p/50V_4  [C0402]  98.57 193.04 0 top
PC9030  *EV@56p/50V_4  [C0402]  101.39 193.82 225 bottom
PC9053  EV@1u/25V_4  [C0402]  92.97 186.8 270 top
PC9054  EV@1u/25V_4  [C0402]  91.05 181.51 90 top
PC9055  EV@10u/6.3V_6  [C0603]  94.79 186.66 0 top
PC9056  EV@0.1u/16V_4  [C0402]  97 186.76 180 top
PC9057  EV@0.1u/16V_4  [C0402]  97.08 182.69 180 top
PC9058  EV@10u/6.3V_6  [C0603]  94.28 181.76 0 top
PC9059  EV@0.1u/16V_4  [C0402]  91.61 184.17 0 top
PC9060  EV@0.1u/16V_4  [C0402]  91.61 183.21 0 top
PC9062  EV@1000p/50V_4  [C0402]  98.82 183.7 90 top
PC9063  EV@1000p/50V_4  [C0402]  97.33 183.66 180 top
PC9064  *EV@820p/50V_4  [C0402]  91.61 185.19 0 top
PC9065  EV@0.1u/16V_4  [C0402]  88.82 191.41 0 bottom
PC9066  EV@10u/6.3V_6  [C0603]  88.82 192.68 0 bottom
PC9067  EV@10u/6.3V_6  [C0603]  91.03 195.09 270 bottom
PC9068  EV@10u/6.3V_6  [C0603]  92.45 195.09 270 bottom
PC9069  EV@0.1u/16V_4  [C0402]  89.81 194.99 270 bottom
PC9071  EV@0.01u/50V_4  [C0402]  102.84 186.7 180 bottom
PC9072  EV@0.1u/16V_4  [C0402]  105.2 185.75 270 bottom
PC9073  *EV@0.1u/16V_4  [C0402]  99.97 182.47 0 bottom
PC9074  *EV@0.01u/50V_4  [C0402]  164.84 154.16 0 top
PC9075  EV@10u/6.3V_6  [C0603]  168.04 159.59 180 bottom
PC9076  *EV@0.1u/25V_4  [C0402]  164.85 152.21 0 top
PC9077  EV@2200p/50V_4  [C0402]  164.84 153.17 0 top
PC9078  EV@10u/25V_8  [C0805]  163.23 150.63 0 bottom
PC9079  EV@0.1u/25V_4  [C0402]  164.41 157.94 180 bottom
PC9080  EV@22u/6.3V_6  [C0603]  166.99 165.29 180 bottom
PC9081  EV@22u/6.3V_6  [C0603]  167.02 162.45 180 bottom
PC9082  EV@22u/6.3V_6  [C0603]  166.99 165.29 180 top
PC9083  EV@22u/6.3V_6  [C0603]  166.99 163.87 180 top
PC9084  EV@22u/6.3V_6  [C0603]  167.02 162.45 180 top
PC9085  *EV@22u/6.3V_6  [C0603]  167.02 161.03 180 bottom
PC9086  *EV@22u/6.3V_6  [C0603]  166.99 163.87 180 bottom
PC9087  EV@0.1u/16V_4  [C0402]  166.64 161.25 180 top
PC9088  *EV@680p/50V_6  [C0603]  164.05 156.1 135 top
PC9089  *EV@1000p/50V_4  [C0402]  169.92 151.3 90 bottom
PC9090  EV@0.22u/10V_4  [C0402]  169.41 156.27 180 bottom
PC9091  EV@0.01u/6.3V_2  [C0201]  168.85 157.1 0 bottom
PC9097  *22p/50V_4  [C0402]  4.95 38.68 180 bottom
PC9098  *22u/6.3V_6  [C0603]  34.21 136.17 0 top
PC9099  *0.1u/6.3V_2  [C0201]  168.09 149.4 270 bottom
PD1  *EV@RB500V-40  [D-SOD323-1_85X1_25-0_95H]  99.33 197.38 180 bottom
PD3  PDZ5.6B  [D-SOD323-1_7X1_25-PMEG4005AEA]  110.41 107.11 0 bottom
PD4  PDZ5.6B  [D-SOD323-1_7X1_25-PMEG4005AEA]  106.98 106.17 180 bottom
PD8000  P4SMAFJ20A  [D-3_8X2_5]  16.9 194.75 0 top
PD8001  PDZ5.1B  [D-SOD323-1_7X1_25-PMEG4005AEA]  81.56 189.18 180 top
PD8002  MMBD4148TS  [D-SOD523-1_2X0_8-1N4148WT-7]  28.34 114.63 0 top
PD8003  MMBD4148TS  [D-SOD523-1_2X0_8-1N4148WT-7]  28.34 113.2 0 top
PD8004  RB521S30  [D-SOD523-1_2X0_8]  17.7 115.34 180 top
PD8005  *RB521S30  [D-SOD523-1_2X0_8]  29.64 106.7 270 top
PD8006  *MMBD4148TS  [D-SOD523-1_2X0_8-1N4148WT-7]  31.26 113.89 180 top
PD8007  *MMBD4148TS  [D-SOD523-1_2X0_8-1N4148WT-7]  31.26 112.47 180 top
PD9001  EV@1SS355  [D-SOD323-1_85X1_25-0_95H]  101.95 188.11 0 bottom
PD9002  BAT54CW  [SOT23-1_7-65-3P]  156.69 122.75 90 top
PJ1  50458-00801-V02  [WTB-50458-00801-V02-8P-L]  107.12 97.92 180 bottom
PJ3008  *0.001_1%_3720  [RC3720-SMT]  9.93 39.06 270 bottom
PJ5000  *Short_0805  [S0805]  82.44 186.79 270 bottom
PJ5001  *short3720  [SHORT3720]  83 181.25 180 top
PJ5002  *short3720  [SHORT3720]  77.13 179.98 90 top
PJ6001  *short3720  [SHORT3720]  195.17 129.71 270 bottom
PJ6003  *short3720  [SHORT3720]  42.79 182.95 90 bottom
PJ7000  *short3720  [SHORT3720]  158.54 159.03 270 top
PJ7001  *short3720  [SHORT3720]  168.83 128.04 270 bottom
PJ8000  SP@30738-11202-001  [DCJK-30738-11202-001-3P]  3 198.95 90 bottom
PJ9002  *short3720  [SHORT3720]  166.12 168 0 bottom
PJ9003  *short3720  [SHORT3720]  95.42 195.02 0 bottom
PJ9005  *short3720  [SHORT3720]  37.13 131.98 0 top
PJ9008  *short3720  [SHORT3720]  92.37 199.79 270 top
PJ9009  *short3720  [SHORT3720]  158.54 163.47 270 top
PJ9010  *short3720  [SHORT3720]  106.55 190.7 270 top
PL5  6.8uH/4.5A_7x7x3  [L6_6X6_6-2_8H]  143.86 115.47 180 bottom
PL14  *2.2uH/1.67A_2.5x2.0x1.2  [L2_5X2-1_2H]  9.62 35.29 90 bottom
PL551  1uH/3.35A_2.5x2.0x1.2  [L2_5X2-1_2H]  37 137.06 270 top
PL5000  1uH/11A_7x7x3  [L6_6X6_6-2_8H]  78.53 181.56 180 bottom
PL5001  2.2uH_2.5x2.0x1.2  [L2_5X2-1_2H]  76.55 186.74 0 bottom
PL6000  1uH/11A_7x7x3  [L6_6X6_6-2_8H]  183.66 129.87 0 bottom
PL6001  1uH/11A_7x7x3  [L6_6X6_6-2_8H]  49.25 181.73 180 bottom
PL7000  0.24uH/28A_7x7x3  [L6_6X6_6-2_8H]  146.73 161.19 270 bottom
PL7001  0.24uH/28A_7x7x3  [L6_6X6_6-2_8H]  146.73 151.79 90 bottom
PL7002  0.22uH/23A_7x7x3  [L6_6X6_6-2_8H]  143.78 129.99 90 bottom
PL9000  EV@0.22uH/23A_7x7x3  [L6_6X6_6-3H]  111.6 200.76 90 bottom
PL9001  EV@0.22uH/23A_7x7x3  [L6_6X6_6-3H]  107.01 208.33 45 bottom
PL9002  EV@0.68uH/15.5A_7x7x3  [L6_6X6_6-3H]  161.75 162.61 90 bottom
PQ1  AONS32304S  [POWER-5_2X5_55-1_27-5P]  66.7 196.64 0 top
PQ2  AONS32306  [POWER-5_2X5_55-1_27-5P]  147.49 123.09 270 top
PQ6  2N7002K  [SOT23-2-95-3P]  57.34 178.1 90 top
PQ9  AOSS32334C  [SOT23-2_38-95-3P]  37.76 128.22 270 top
PQ12  *2N7002K  [SOT23-2-95-3P]  99.84 96.03 270 top
PQ16  DDTC144EUA-7-F  [SOT23-1_7-65-3P]  54.05 177.9 0 top
PQ17  2N7002KW  [SOT23-1_7-65-3P]  161.41 121.37 180 top
PQ19  *2N7002K  [SOT23-2-95-3P]  18.63 146.72 270 top
PQ29  AONR32320C  [POWER-3X3-65-5P-ADNR21357]  150.57 115.92 0 bottom
PQ30  AONR32320C  [POWER-3X3-65-5P-ADNR21357]  150.39 120.06 270 bottom
PQ5000  AONR36326C  [POWER-3X3-65-5P-ADNR21357]  85.26 183.31 0 bottom
PQ5001  AONR32320C  [POWER-3X3-65-5P-ADNR21357]  85.21 179.19 90 bottom
PQ6000  2N7002K  [SOT23-2-95-3P]  170.61 132.86 90 bottom
PQ6001  2N7002K  [SOT23-2-95-3P]  60.37 186.08 270 bottom
PQ7000  AOE6936  [POWER-5X6-1_27-10P]  147.24 143.66 180 bottom
PQ7001  AOE6936  [POWER-5X6-1_27-10P]  153.72 163.09 270 bottom
PQ7002  AONS36380  [POWER-5_2X5_55-1_27-5P]  156.41 128.34 180 bottom
PQ7003  AONS36312  [POWER-5_2X5_55-1_27-5P]  150.16 128.95 90 bottom
PQ8000  PJA138K  [SOT23-2-95-3P]  51 198.95 180 top
PQ8001  AONS21357  [POWER-5_2X5_55-1_27-5P]  60.5 202.84 270 top
PQ8002  AONS21357  [POWER-5_2X5_55-1_27-5P]  38.27 105.31 180 top
PQ8003  BSS84  [SOT23-2-95-3P]  55.75 199.06 270 top
PQ8004  BSS84  [SOT23-2-95-3P]  33.73 99.82 90 top
PQ8005  2N7002KDW  [SOT363-2_1-65-6P]  36.97 99.47 0 top
PQ8006  AONS21357  [POWER-5_2X5_55-1_27-5P]  40.3 111.66 90 top
PQ8007  AONS21357  [POWER-5_2X5_55-1_27-5P]  66.11 202.84 270 top
PQ8008  PMBT3906  [SOT23-2-95-3P]  55.04 193.7 90 top
PQ8009  BSS84  [SOT23-2-95-3P]  34.29 117.27 180 top
PQ8010  BSS84  [SOT23-2-95-3P]  81.48 191.99 270 top
PQ8011  PMBT3906  [SOT23-2-95-3P]  51.38 193.87 0 top
PQ8012  MMDT2907A-7-F  [SOT363-2_1-65-6P]  37.79 117.52 90 top
PQ8013  MMDT2907A-7-F  [SOT363-2_1-65-6P]  86.91 189.23 0 top
PQ8014  PJA3411  [SOT23-2-95-3P]  20.67 114.26 90 top
PQ8015  2N7002K  [SOT23-2-95-3P]  29.74 117.12 0 top
PQ8016  MMDT2907A-7-F  [SOT363-2_1-65-6P]  24.43 114.4 90 top
PQ8017  *PJA3411  [SOT23-2-95-3P]  29.87 109.57 270 top
PQ8018  *MMDT2907A-7-F  [SOT363-2_1-65-6P]  26.59 110.61 270 top
PQ8019  *2N7002K  [SOT23-2-95-3P]  22.02 110.82 180 top
PQ9000  EV@AOE6936  [POWER-5X6-1_27-10P]  100.63 202.71 90 bottom
PQ9001  EV@AOE6936  [POWER-5X6-1_27-10P]  110.66 193.37 180 bottom
PQ9008  EV@AONR32320C  [DFN-8L-3X3-65-5P-0_9H]  91.89 191.23 90 bottom
PQ9009  EV@2N7002K  [SOT23-2-95-3P]  97.71 189.35 270 bottom
PQ9010  EV@DMG1012T-7  [SOT23-1_38-5-3P]  104.64 189.58 0 bottom
PQ9011  EV@2N7002K  [SOT23-2-95-3P]  101.42 190.7 90 bottom
PQ9050  2N7002K  [SOT23-2-95-3P]  37 122.48 270 top
PQ9054  AONS32304S  [POWER-5_2X5_55-1_27-5P]  72.72 202.84 270 top
PQ9083  EV@LTC044EUBFS8TL  [SOT23-1_7-65-3P]  161.23 209.82 180 top
PQ9084  EV@2N7002KW  [SOT23-1_7-65-3P]  158.18 169.83 180 top
PQ9085  EV@2N7002K  [SOT23-2-95-3P]  163.14 167.51 180 top
PQ9086  EV@DMG1012T-7  [SOT23-1_38-5-3P]  159.23 167.13 270 top
PQ9087  AOSS32334C  [SOT23-2_38-95-3P]  29 142.14 90 top
PQ9088  2N7002K  [SOT23-2-95-3P]  25.19 142.14 90 top
PR1  *Short_0201  [S0201]  76.88 200.56 90 top
PR2  *Short_0201  [S0201]  77.64 200.56 90 top
PR3  0.01_1%_0612  [RC3216]  77.26 203.6 90 top
PR4  0_5%_6  [R0603]  150.24 117.62 90 top
PR5  *Short_0201  [S0201]  157.53 115.19 270 bottom
PR6  *Short_0201  [S0201]  158.26 115.19 270 bottom
PR7  10_1%_6  [R0603]  148.18 117.01 180 top
PR8  *Short_0201  [S0201]  162.17 116.53 90 bottom
PR9  10K_5%_4  [R0402]  161.23 115.16 90 bottom
PR10  *0_5%_2  [R0201]  104.06 104.67 0 bottom
PR11  0_5%_6  [R0603]  153.94 119.5 0 top
PR12  100_5%_4  [R0402]  109.19 105.31 270 bottom
PR13  100_5%_4  [R0402]  110.15 105.31 270 bottom
PR14  100_5%_4  [R0402]  105.96 104.72 0 bottom
PR15  *10K_5%_4  [R0402]  163.55 115.34 90 bottom
PR16  20_5%_12  [R1206]  155.14 123.62 0 bottom
PR17  *Short_0201  [S0201]  163.24 116.97 0 bottom
PR18  1M_5%_4  [R0402]  162.22 115.16 90 bottom
PR19  *Short_0201  [S0201]  162.89 117.89 0 bottom
PR22  *100K_1%_2  [R0201]  163.24 118.89 0 bottom
PR23  *SP@20.5K_1%_4  [R0402]  165.21 120.19 180 bottom
PR25  *Short_0201  [S0201]  163.24 119.81 0 bottom
PR26  *Short_0201  [S0201]  163.77 120.85 90 bottom
PR28  4.02K_1%_4  [R0402]  160.91 123.33 0 bottom
PR29  4.02K_1%_4  [R0402]  162.27 122.88 90 bottom
PR30  *Short_0201  [S0201]  159.54 121.3 270 top
PR31  93.1K_1%_4  [R0402]  163.99 122.92 180 top
PR32  *Short_0201  [S0201]  162.73 121.33 0 bottom
PR33  *4.7_5%_6  [R0603]  149.91 113.18 180 bottom
PR39  100K_1%_4  [R0402]  156.87 119.78 270 top
PR40  100K_1%_4  [R0402]  158.48 121.42 90 top
PR59  1M_5%_6  [R0603]  59.79 181.38 90 top
PR106  *22_5%_8  [R0805]  98.72 98.7 180 top
PR116  1M_5%_6  [R0603]  57.7 181.89 0 top
PR118  1M_5%_6  [R0603]  55.04 181.89 0 top
PR120  *100K_1%_6  [R0603]  55.44 175.84 180 top
PR126  *220_5%_8  [R0805]  15.83 146.85 90 top
PR204  316K_1%_4  [R0402]  155.24 115.11 180 bottom
PR205  *0_5%_2  [R0201]  161.46 116.96 90 bottom
PR206  100K_1%_4  [R0402]  154.91 116.53 270 bottom
PR207  100K_5%_4  [R0402]  160.98 118.61 0 top
PR208  0_5%_2  [R0201]  139.24 111.66 90 top
PR209  0.01_1%_0612  [RC3216]  139.36 114.2 270 top
PR210  0_5%_2  [R0201]  140 111.66 270 top
PR211  27.4K_1%_4  [R0402]  164.26 120.91 270 top
PR230  220K_1%_4  [R0402]  56.97 204.21 270 top
PR235  1M_5%_4  [R0402]  56.97 202.18 270 top
PR283  *15K_1%_4  [R0402]  5 36.65 180 bottom
PR284  *0_5%_2  [R0201]  5.94 31.7 180 bottom
PR551  *2.2_5%_6  [R0603]  34.59 138.58 270 top
PR566  *Short_0201  [S0201]  38.65 139.85 0 top
PR567  10K_1%_2  [R0201]  37.63 143.65 270 top
PR568  20K_1%_4  [R0402]  38.65 143.91 90 top
PR569  *Short_0201  [S0201]  38.91 136.55 180 top
PR3020  150_5%_4  [R0402]  133.14 112.54 270 bottom
PR3021  25.5K_1%_4  [R0402]  131.59 119.43 0 bottom
PR3022  *Short_0201  [S0201]  133.55 117.5 270 bottom
PR5000  100K_1%_2  [R0201]  69.31 185.24 180 bottom
PR5001  100K_1%_2  [R0201]  93.26 180.18 270 top
PR5002  *Short_0201  [S0201]  92.37 179.98 90 top
PR5003  *0_5%_2  [R0201]  91.69 169.8 90 top
PR5004  *Short_0201  [S0201]  92.45 170.38 270 top
PR5005  316K_1%_4  [R0402]  89.71 179.22 180 top
PR5006  *0_5%_2  [R0201]  90.98 169.8 90 top
PR5007  499K_1%_4  [R0402]  92.71 178.61 90 top
PR5008  2.2_5%_6  [R0603]  86.76 177.26 90 top
PR5009  100_5%_2  [R0201]  90.22 172.49 0 top
PR5010  *4.7_5%_6  [R0603]  84.37 186.66 270 bottom
PR5011  *Short_0402  [S0402]  89.71 181.1 0 top
PR5012  *Short_0201  [S0201]  69.39 179.35 270 bottom
PR5013  *0_5%_2  [R0201]  91.44 170.66 0 top
PR5014  *Short_0201  [S0201]  89.2 172.49 180 top
PR5015  0_5%_2  [R0201]  90.24 169.8 90 top
PR5016  *Short_0201  [S0201]  91.36 179.35 180 top
PR5017  *0_5%_2  [R0201]  91.36 180.18 0 top
PR5018  8.2K_1%_2  [R0201]  92.12 174.04 180 top
PR5019  10K_1%_2  [R0201]  92.12 173.33 180 top
PR5020  *Short_0603  [S0603]  70.66 185.06 90 top
PR5021  *Short_0201  [S0201]  69.31 185.95 180 bottom
PR5022  *Short_0201  [S0201]  77.01 185.32 0 top
PR5023  *0_5%_2  [R0201]  73.83 190.14 0 bottom
PR5024  *Short_0201  [S0201]  74.16 188.69 180 bottom
PR5025  *Short_0201  [S0201]  72.82 188.67 180 bottom
PR5026  47.5K_1%_2  [R0201]  71.34 188.69 0 bottom
PR5027  15K_1%_2  [R0402]  69.26 187.22 90 bottom
PR6000  10_1%_6  [R0603]  178.53 133.98 0 bottom
PR6001  *4.7_5%_6  [R0603]  181.88 124.99 90 bottom
PR6002  *Short_0201  [S0201]  175.79 134.04 0 top
PR6003  10K_1%_2  [R0201]  173.76 130.55 0 top
PR6004  *Short_0201  [S0201]  173.27 129.44 0 bottom
PR6005  *Short_0201  [S0201]  174.29 129.44 0 bottom
PR6006  10K_1%_2  [R0201]  174.04 128.67 0 bottom
PR6007  100K_1%_2  [R0201]  176.02 129.89 0 top
PR6008  *Short_0201  [S0201]  193.87 127.15 180 bottom
PR6009  10K_1%_2  [R0201]  175.79 132.79 270 top
PR6010  *1K_1%_4  [R0402]  174.7 134.06 90 bottom
PR6011  1K_1%_4  [R0402]  173.27 134.36 180 bottom
PR6012  *100K_1%_4  [R0402]  171.37 135.4 270 bottom
PR6013  *Short_0402  [S0402]  202.23 129.56 180 top
PR6014  *10K_1%_4  [R0402]  175.69 134.08 90 bottom
PR6015  *Short_0201  [S0201]  199.31 126.9 90 top
PR6016  *Short_0201  [S0201]  198.42 130.96 0 top
PR6017  *0_5%_6  [R0603]  173.83 132.23 180 top
PR6018  10_1%_6  [R0603]  55.82 179.37 270 bottom
PR6019  *4.7_5%_6  [R0603]  50.92 178.61 0 top
PR6020  *Short_0201  [S0201]  57.58 187.35 180 bottom
PR6021  10K_1%_2  [R0201]  57.58 186.59 180 bottom
PR6022  *Short_0201  [S0201]  57.58 185.82 180 bottom
PR6023  *Short_0402  [S0402]  35.73 168.81 270 top
PR6024  *100K_1%_4  [R0402]  61.82 183.28 270 bottom
PR6025  *Short_0603  [S0603]  59.33 178.74 0 bottom
PR6026  *Short_0201  [S0201]  45.12 178.39 180 bottom
PR6027  *Short_0201  [S0201]  36.62 168.55 270 top
PR6028  *Short_0201  [S0201]  34.72 168.55 270 top
PR6029  1K_1%_4  [R0402]  61.44 180.79 0 bottom
PR6030  *1K_1%_4  [R0402]  60.07 181.35 90 bottom
PR6031  *10K_1%_4  [R0402]  59.1 183.05 90 bottom
PR6414  *Short_0201  [S0201]  6.27 38.43 270 bottom
PR6416  *100K_1%_2  [R0201]  6.93 31.9 180 bottom
PR6417  *0_5%_2  [R0201]  4.74 40.71 0 bottom
PR6418  *22.6K_1%_2  [R0201]  5.15 37.69 180 bottom
PR7000  20K_1%_2  [R0201]  166.45 147.23 0 top
PR7001  0_5%_4  [R0402]  161.36 149.91 90 top
PR7002  6.2_5%_6  [R0603]  161.41 147.6 315 top
PR7003  2.2_5%_6  [R0603]  155.24 145.01 180 bottom
PR7004  100_1%_2  [R0201]  164.41 148.74 0 top
PR7005  *75_1%_2  [R0201]  163.34 148.74 0 top
PR7006  45.3_1%_2  [R0201]  164.35 148 0 top
PR7007  *10K_1%_2  [R0201]  162.35 149.15 180 top
PR7008  2.2_5%_6  [R0603]  159.48 148.54 225 top
PR7009  1_5%_6  [R0603]  151.3 140.81 0 bottom
PR7010  *2.2_5%_6  [R0603]  143.73 146.38 270 bottom
PR7011  *Short_2  [S0201]  146.73 150.01 90 bottom
PR7012  *Short_2  [S0201]  146.73 153.57 270 bottom
PR7013  3.9_5%_4  [R0402]  161.51 144.6 315 top
PR7014  54.9K_1%_2  [R0201]  164.51 144.85 0 top
PR7015  9.31K_1%_2  [R0201]  164.49 146.05 0 top
PR7016  22.1K_1%_2  [R0201]  164.46 147.24 0 top
PR7017  174K_1%_2  [R0201]  158.92 142.9 180 top
PR7018  110_1%_2  [R0201]  165.53 144.85 0 top
PR7019  182_1%_2  [R0201]  165.48 146.05 0 top
PR7020  200_1%_2  [R0201]  165.45 147.24 0 top
PR7021  1.91K_1%_2  [R0201]  157.93 142.9 180 top
PR7022  100K_NTC_4_1%  [R0402]  149.35 139.29 90 bottom
PR7023  10_1%_2  [R0201]  157.04 143.48 270 top
PR7024  1_5%_6  [R0603]  156.87 167.08 0 bottom
PR7025  110K_1%_2  [R0201]  157.14 143.41 270 bottom
PR7026  10K_1%_2  [R0201]  166.52 144.85 0 top
PR7027  8.06K_1%_2  [R0201]  166.47 146.17 180 top
PR7028  8.25K_1%_2  [R0201]  157.93 143.61 0 top
PR7029  *2.2_5%_6  [R0603]  149.22 166.87 0 bottom
PR7030  *Short_2  [S0201]  146.73 162.99 270 bottom
PR7031  *Short_2  [S0201]  146.73 159.41 90 bottom
PR7032  3.3K_1%_2  [R0201]  167.51 144.85 180 top
PR7033  60.4_1%_2  [R0201]  167.46 146.17 0 top
PR7034  301_1%_2  [R0201]  167.43 147.22 0 top
PR7035  402_1%_2  [R0201]  158.92 143.61 0 top
PR7036  2.43K_1%_4  [R0402]  156.1 139.77 90 bottom
PR7037  3.32K_1%_4  [R0402]  157.07 139.77 270 bottom
PR7038  3.83K_1%_4  [R0402]  156.87 141.12 180 bottom
PR7039  680_1%_2  [R0201]  158.52 141.91 90 bottom
PR7040  10K_1%_2  [R0201]  155.39 142.92 0 bottom
PR7041  *Short_0201  [S0201]  155.47 143.79 90 bottom
PR7042  *Short_0201  [S0201]  162.35 149.12 180 bottom
PR7043  *Short_0201  [S0201]  164.35 148 180 bottom
PR7044  2.43K_1%_4  [R0402]  161.36 139.29 90 bottom
PR7045  3.32K_1%_4  [R0402]  160.4 139.29 270 bottom
PR7046  *Short_0201  [S0201]  164.41 148.74 180 bottom
PR7047  3.83K_1%_4  [R0402]  160.75 140.66 0 bottom
PR7048  680_1%_2  [R0201]  159.24 141.91 90 bottom
PR7049  *Short_0201  [S0201]  163.34 148.71 180 bottom
PR7050  0_5%_2  [R0201]  155.65 141.14 90 bottom
PR7051  *Short_0201  [S0201]  167.43 144.55 90 bottom
PR7052  100_1%_2  [R0201]  140.63 154.84 270 top
PR7053  SP@20.5K_1%_4  [R0402]  166.54 144.42 90 bottom
PR7054  23.2K_1%_4  [R0402]  162.76 140.08 0 bottom
PR7055  10K_1%_4  [R0402]  164.49 140.2 180 bottom
PR7056  *Short_0201  [S0201]  141.52 154.45 90 top
PR7057  *Short_0201  [S0201]  141.52 153.44 270 top
PR7058  100_1%_2  [R0201]  140.63 153.06 90 top
PR7059  3.01K_1%_4  [R0402]  163.67 143 180 top
PR7060  100K_NTC_4_1%  [R0402]  142.49 148.28 270 bottom
PR7061  18.2K_1%_4  [R0402]  164.43 144.12 0 bottom
PR7062  17.4K_1%_4  [R0402]  164.43 143.96 180 top
PR7063  *0_5%_4  [R0402]  160.14 137.94 180 bottom
PR7064  *100K_1%_2  [R0201]  162.35 138.83 270 bottom
PR7065  *100K_1%_2  [R0201]  161.51 137.94 0 bottom
PR7066  2.2_5%_6  [R0603]  156.74 136.95 90 bottom
PR7067  *100K_1%_2  [R0201]  163.11 138.66 90 bottom
PR7068  *100K_1%_2  [R0201]  161.51 137.23 180 bottom
PR7070  158K_1%_4  [R0402]  167.18 136.42 0 bottom
PR7071  1_5%_6  [R0603]  154.33 131.9 0 bottom
PR7072  5.1_1%_6  [R0603]  159.38 135.18 90 bottom
PR7073  10K_1%_2  [R0201]  166.67 134.46 0 bottom
PR7074  *Short_0201  [S0201]  167.69 134.46 180 bottom
PR7075  *2.2_5%_6  [R0603]  147.75 129.69 90 top
PR7076  *Short_0201  [S0201]  162.38 137.11 270 bottom
PR7077  *Short_0201  [S0201]  163.11 137.11 270 bottom
PR7078  *10K_1%_4  [R0402]  165.35 137.77 0 bottom
PR7079  0_5%_4  [R0402]  166.9 135.43 180 bottom
PR7080  *Short_0201  [S0201]  164.99 138.6 0 bottom
PR7081  0_5%_4  [R0402]  163.04 131.01 270 bottom
PR7082  *0_5%_2  [R0201]  165.98 138.6 180 bottom
PR7083  10K_1%_4  [R0402]  167.89 132.58 0 bottom
PR7084  *1.4K_1%_4  [R0402]  165.5 129.94 180 bottom
PR7085  100_1%_2  [R0201]  129.97 149.37 270 bottom
PR7086  100K_1%_4  [R0402]  161.97 131.01 270 bottom
PR7087  6.34K_1%_4  [R0402]  164.99 131.29 90 bottom
PR7088  *Short_0201  [S0201]  129.2 149.37 270 bottom
PR7089  100K_1%_4  [R0402]  160.95 131.01 270 bottom
PR7090  *Short_0201  [S0201]  129.2 150.39 90 bottom
PR7091  100_1%_2  [R0201]  129.97 150.39 90 bottom
PR8000  100K_1%_2  [R0201]  38.25 115.57 0 top
